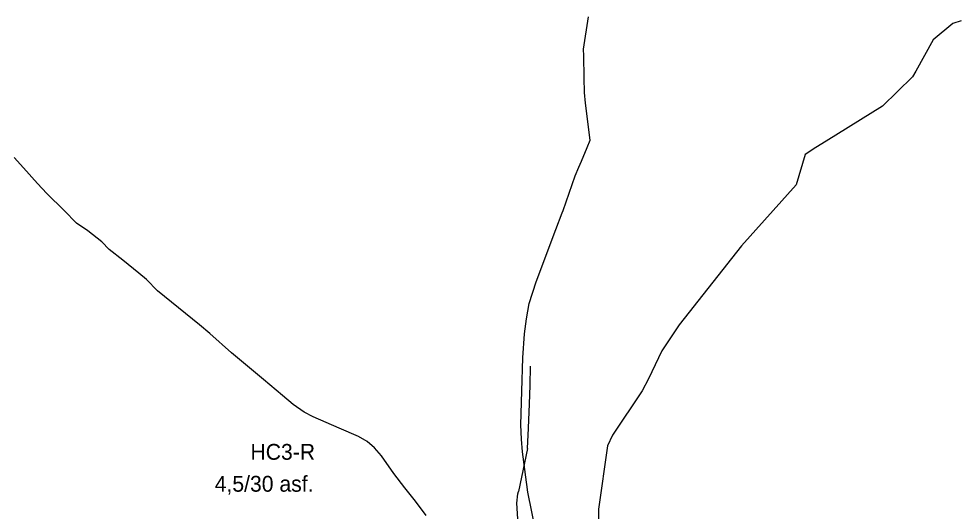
# Model space of a CAD drawing. Extents: x -543464 to -538545, y -1098769 to -1093672.
# Drawn here: x -541951 to -540640, y -1096101 to -1095417 of the extents above; entities that cross this region are included whole.
import ezdxf

# ---------------------------------------------------------------- set-up
doc = ezdxf.new("R2010")
doc.units = 0
for name, color, linetype in [('03_PC_NAVRH', 7, 'Continuous'), ('03_PC_POPIS_NAVRH', 7, 'Continuous'), ('07_ELEKTRO', 7, 'Continuous'), ('07_SDĚLOVACÍ', 7, 'Continuous'), ('07_VODOVOD', 7, 'Continuous')]:
    doc.layers.add(name, color=color, linetype=linetype)

msp = doc.modelspace()

# ---------------------------------------------------------------- linework, layer by layer
at = {"layer": '03_PC_NAVRH'}
msp.add_lwpolyline([(-541384.6, -1096107), (-541399.2, -1096086.8), (-541414.2, -1096068.4), (-541429.6, -1096048.4), (-541446.5, -1096024), (-541456.1, -1096012.9), (-541466.7, -1096004), (-541478.6, -1095997.3), (-541505.3, -1095985.3), (-541541.7, -1095969.9), (-541554, -1095963.3), (-541569.4, -1095952.7), (-541584.4, -1095940.1), (-541610.8, -1095918), (-541655, -1095881), (-541685.4, -1095854.1), (-541699.8, -1095842.1), (-541758.2, -1095794.5), (-541773.3, -1095779.1), (-541784.1, -1095770.2), (-541806.3, -1095751.9), (-541825.4, -1095737), (-541835.4, -1095726.7), (-541854.9, -1095711.1), (-541870.5, -1095700.4), (-541887.7, -1095683.1), (-541912.1, -1095659.2), (-541925, -1095645.5), (-541944.3, -1095623.5), (-541957.3, -1095609.5)], dxfattribs=at)
at = {"layer": '07_ELEKTRO'}
for points in [[(-541240, -1095926.3), (-541239.2, -1095899.1)], [(-541240.6, -1095951.6), (-541240, -1095926.3)], [(-541242.3, -1095985.6), (-541240.6, -1095951.6)], [(-541243.5, -1096013.6), (-541242.3, -1095985.6)], [(-541243.5, -1096013.6), (-541256.2, -1096073.3)], [(-541259.6, -1096207.1), (-541259.4, -1096207.5), (-541257.6, -1096208.1), (-541251, -1096213.4), (-541247, -1096214.8), (-541243.1, -1096215.1), (-541239.3, -1096213.5), (-541238.7, -1096211.9), (-541238.3, -1096195.5), (-541239.5, -1096186.8), (-541243.5, -1096168.3), (-541248.2, -1096148.8), (-541251.5, -1096136.9), (-541253.8, -1096127.9), (-541255.9, -1096120.3), (-541257.1, -1096111.6), (-541258.3, -1096089.5), (-541257, -1096076.8), (-541256.2, -1096073.3)]]:
    msp.add_lwpolyline(points, dxfattribs=at)
at = {"layer": '07_SDĚLOVACÍ'}
for points in [[(-541160.4, -1095595.5), (-541156.6, -1095585), (-541162.8, -1095534), (-541164.4, -1095519.1), (-541164.9, -1095498.4), (-541165.3, -1095468.2), (-541165.5, -1095458.6), (-541158.6, -1095413.9)], [(-541177.1, -1095635), (-541172, -1095622.9), (-541168.2, -1095614.4), (-541160.4, -1095595.5)], [(-541241.3, -1095812.4), (-541231.5, -1095782.3), (-541204.2, -1095709.6), (-541195.3, -1095686.3), (-541193.9, -1095683.1), (-541177.1, -1095635)], [(-541247.8, -1095854.4), (-541244.7, -1095833.5), (-541241.3, -1095812.4)], [(-541231.4, -1096131.6), (-541243.1, -1096074.5), (-541244.5, -1096063.6), (-541244.8, -1096060.5), (-541250.6, -1096018.2), (-541251.9, -1096000.6), (-541252.6, -1095980.8), (-541251.5, -1095934.1), (-541250.1, -1095887.7), (-541247.8, -1095854.4)]]:
    msp.add_lwpolyline(points, dxfattribs=at)
at = {"layer": '07_VODOVOD'}
for points in [[(-540640.5, -1095419.3), (-540652.2, -1095423), (-540679.2, -1095445.6), (-540703.6, -1095489.3), (-540708, -1095497), (-540750, -1095538), (-540828.1, -1095586.5), (-540842.4, -1095595.5), (-540857.5, -1095605.2)], [(-540857.5, -1095605.2), (-540869.9, -1095647.3), (-540946, -1095732), (-541032.6, -1095842.1), (-541056.7, -1095877.8), (-541075.4, -1095916.8), (-541084.1, -1095933.7), (-541125.2, -1095995.3), (-541132.3, -1096010.2), (-541144.9, -1096098.2), (-541144.7, -1096123.8), (-541138.4, -1096160.4), (-541179.7, -1096268.5), (-541189.3, -1096297.7), (-541189.9, -1096300)]]:
    msp.add_lwpolyline(points, dxfattribs=at)

# ---------------------------------------------------------------- texts
at = {"layer": '03_PC_POPIS_NAVRH'}
for s, p in [('HC3-R', (-541628.8, -1096029.4)), ('4,5/30 asf.', (-541678.5, -1096073.8))]:
    msp.add_text(s, height=22, dxfattribs=at).set_placement(p)

doc.saveas('drawing.dxf')
